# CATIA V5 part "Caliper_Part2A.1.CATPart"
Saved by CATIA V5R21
Part number: Caliper_Part2A.1
Property "V_Scale": "NormalScale"
Property "V_isTerminal": "true"
Property "V_ChangeHistory": "false"
Property "V_isLastVersion": "false"
Property "V_isVPLMControlled": "true"
Property "V_AuthorityControl": "false"
Property "V_ProjectApplicability": "List"
Property "V_Name": "Caliper_Part2"
Property "PLM_ExternalID": "prd-R1132100306978-00000010"
Property "V_description": " "
Property "V_usage": "3DPart"
Property "V_nature": "Definition"
Property "V_sec_level": "0"
Property "owner": "lightandshadows"
Property "project": "Common Space"
Property "organization": "Company Name"
Property "revision": "A.1"
Property "originated": "10/07/2015 :: 02:19:47 "
Property "modified": "06/20/2017 :: 04:59:00 "
Property "reserved": "false"
Property "current": "IN_WORK"
Property "name": "prd-R1132100306978-00000010"
Property "locked": "false"
Property "revindex": "0"
Property "isbestsofar": "true"
Property "minorrevision": "1"
Property "majorrevision": "A"
Property "ispublished": "false"
Property "policy": "VPLM_SMB_Definition"
Bounding box of the stored display mesh (mm): x -87 to 83, y -159 to -97.655, z -30.2 to 63.8
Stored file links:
  E:\Desktop\AXEL\A1\Caliper_Part2A.1.CATPart

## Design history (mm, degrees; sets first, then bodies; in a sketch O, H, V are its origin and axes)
Body1 "MANIFOLD_SOLID_BREP #4384" (main body)
  Solid1: solid without history
Body2 "MANIFOLD_SOLID_BREP #4385"
  Solid2: solid without history
Body3 "MANIFOLD_SOLID_BREP #4386"
  Solid3: solid without history
Body4 "MANIFOLD_SOLID_BREP #4387"
  Solid4: solid without history
Body5 "MANIFOLD_SOLID_BREP #4388"
  Solid5: solid without history
Body6 "MANIFOLD_SOLID_BREP #4389"
  Solid6: solid without history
